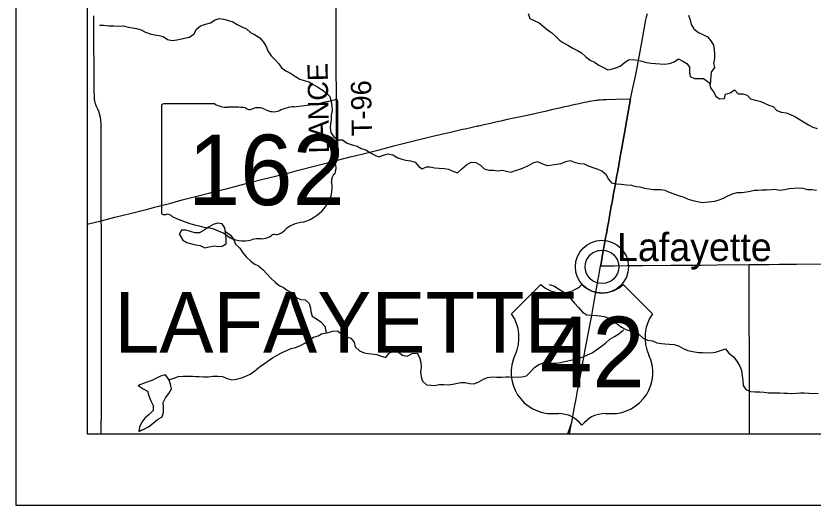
# Model space of a CAD drawing. Extents: x 0 to 34, y 0 to 22.
# Drawn here: x 2 to 3.119, y 14 to 14.686 of the extents above; entities that cross this region are included whole.
import ezdxf

# ---------------------------------------------------------------- set-up
doc = ezdxf.new("R2010")
doc.units = 0
for name, color, linetype in [('GM_X_County_Road', 7, 'Continuous'), ('GM_X_Minor_Lake', 7, 'Continuous'), ('GM_X_Minor_River', 7, 'Continuous'), ('GM_X_Rail_Line_Text', 7, 'Continuous'), ('GM_X_State_Location', 7, 'Continuous'), ('GM_X_State_Route', 7, 'Continuous'), ('GM_X_State_Shield', 7, 'Continuous'), ('GM_X_Township_Road', 7, 'Continuous'), ('GM_X_Township_Road_Text', 7, 'Continuous'), ('GM_X_Township_Text', 7, 'Continuous'), ('GM_X_Unincorporated', 7, 'Continuous'), ('GM_X_Unincorporated_Location', 7, 'Continuous'), ('GM_X_Unincorporated_Text', 7, 'Continuous'), ('GM_X_US_Location', 7, 'Continuous'), ('GM_X_US_Route', 7, 'Continuous'), ('GM_X_US_Shield', 7, 'Continuous'), ('SH_Cut_Line', 7, 'Continuous'), ('SH_Data', 7, 'Continuous')]:
    doc.layers.add(name, color=color, linetype=linetype)

msp = doc.modelspace()

# ---------------------------------------------------------------- linework, layer by layer
at = {"layer": 'GM_X_County_Road'}
msp.add_lwpolyline([(2.7775, 14.1), (2.7794, 14.1099), (2.7798, 14.1121), (2.7803, 14.1148), (2.7807, 14.1169)], dxfattribs=at)
at = {"layer": 'GM_X_Minor_Lake'}
for points in [[(2.2941, 14.3826), (2.2933, 14.3892), (2.2895, 14.3945), (2.2832, 14.3955), (2.2768, 14.3938), (2.2705, 14.3899), (2.2644, 14.3857), (2.2578, 14.3819), (2.2513, 14.3821), (2.2452, 14.3838), (2.2388, 14.3857), (2.2323, 14.3857), (2.2294, 14.3795)], [(2.2941, 14.383), (2.2933, 14.3892), (2.2895, 14.3945), (2.2832, 14.3955), (2.2768, 14.3938), (2.2705, 14.3899), (2.2644, 14.3857), (2.2578, 14.3819), (2.2513, 14.3821), (2.2452, 14.3838), (2.2388, 14.3857), (2.2323, 14.3857), (2.2296, 14.38)], [(2.2296, 14.38), (2.2342, 14.3718), (2.2398, 14.3684), (2.2464, 14.3665), (2.2525, 14.365), (2.2586, 14.3641), (2.2651, 14.361), (2.2714, 14.3624), (2.2782, 14.3639), (2.2851, 14.363), (2.2898, 14.3632), (2.2953, 14.3666), (2.2951, 14.3731), (2.2941, 14.383)], [(2.2298, 14.3797), (2.2342, 14.3718), (2.2398, 14.3684), (2.2464, 14.3665), (2.2525, 14.365), (2.2586, 14.3641), (2.2651, 14.361), (2.2714, 14.3624), (2.2782, 14.3639), (2.2851, 14.363), (2.2898, 14.3632), (2.2953, 14.3666), (2.2951, 14.3731), (2.2941, 14.383)], [(2.2148, 14.176), (2.21, 14.1827), (2.2032, 14.1808), (2.1965, 14.1774), (2.1908, 14.1747), (2.184, 14.1724), (2.1779, 14.1699), (2.1718, 14.1676), (2.1785, 14.1629), (2.1846, 14.1597), (2.1867, 14.1532), (2.1892, 14.1464), (2.1925, 14.1396), (2.1927, 14.1327), (2.1872, 14.1272), (2.181, 14.1221), (2.1766, 14.1162), (2.1736, 14.1095), (2.1725, 14.1034)], [(2.2147, 14.1762), (2.21, 14.1827), (2.2032, 14.1808), (2.1965, 14.1774), (2.1908, 14.1747), (2.184, 14.1724), (2.1779, 14.1699), (2.1718, 14.1676), (2.1785, 14.1629), (2.1846, 14.1597), (2.1867, 14.1532), (2.1892, 14.1464), (2.1925, 14.1396), (2.1927, 14.1327), (2.1872, 14.1272), (2.181, 14.1221), (2.1766, 14.1162), (2.1736, 14.1095), (2.1725, 14.1032)], [(2.1725, 14.1034), (2.1806, 14.1069), (2.1863, 14.1099), (2.1928, 14.1151), (2.199, 14.1202), (2.2053, 14.124), (2.207, 14.1303), (2.2072, 14.1371), (2.2069, 14.144), (2.2101, 14.1504), (2.2147, 14.1567), (2.2185, 14.1632), (2.2169, 14.1696), (2.2148, 14.176)], [(2.1728, 14.1035), (2.1806, 14.1069), (2.1863, 14.1099), (2.1928, 14.1151), (2.199, 14.1202), (2.2053, 14.124), (2.207, 14.1303), (2.2072, 14.1371), (2.2069, 14.144), (2.2101, 14.1504), (2.2147, 14.1567), (2.2185, 14.1632), (2.2169, 14.1696), (2.2146, 14.1765)]]:
    msp.add_lwpolyline(points, dxfattribs=at)
at = {"layer": 'GM_X_Minor_River'}
for points in [[(2.7193, 14.6897), (2.7218, 14.683), (2.7288, 14.6797), (2.7348, 14.6769), (2.7403, 14.6719), (2.7463, 14.667), (2.7523, 14.6625), (2.7577, 14.6579), (2.7633, 14.6526), (2.769, 14.6487), (2.775, 14.6452), (2.7818, 14.6413), (2.7886, 14.6377), (2.7944, 14.6346), (2.8002, 14.6288), (2.8062, 14.6243)], [(2.9443, 14.6874), (2.9467, 14.681), (2.9481, 14.6744), (2.9521, 14.6684), (2.9583, 14.6632), (2.9644, 14.6602), (2.971, 14.6572), (2.9758, 14.6516), (2.9795, 14.6455), (2.9806, 14.6392), (2.981, 14.6331), (2.9809, 14.6265), (2.9796, 14.6198), (2.9809, 14.6141), (2.9764, 14.6077), (2.9747, 14.5896)], [(2.1174, 14.6734), (2.1235, 14.6733), (2.1306, 14.6724), (2.1376, 14.6725), (2.1446, 14.6722), (2.1511, 14.6724), (2.1575, 14.6708), (2.1636, 14.6699), (2.1693, 14.6689), (2.1759, 14.6667), (2.182, 14.6637), (2.1884, 14.6615), (2.1944, 14.6599), (2.2009, 14.659), (2.2068, 14.6576), (2.213, 14.6533), (2.2194, 14.6518), (2.2257, 14.653), (2.2305, 14.6539), (2.2368, 14.6553), (2.2433, 14.6567), (2.2498, 14.6608), (2.2534, 14.6676), (2.2593, 14.6724), (2.2662, 14.6749), (2.2731, 14.6767), (2.2797, 14.6808), (2.2856, 14.6827), (2.292, 14.6819), (2.2983, 14.68), (2.3045, 14.678), (2.3107, 14.6745), (2.3172, 14.6713), (2.3236, 14.6684), (2.3292, 14.6631), (2.335, 14.6602), (2.3424, 14.6557), (2.3476, 14.6497), (2.3513, 14.6434), (2.3535, 14.6374), (2.3583, 14.6305), (2.3641, 14.6249), (2.3691, 14.6191), (2.3732, 14.6133), (2.3798, 14.6088), (2.3857, 14.6061), (2.3924, 14.6014), (2.3986, 14.5975), (2.4049, 14.5959), (2.4113, 14.5938), (2.4172, 14.5903), (2.4239, 14.5862), (2.43, 14.5827), (2.436, 14.5782), (2.441, 14.5734), (2.4426, 14.5665), (2.4435, 14.56), (2.4441, 14.5537), (2.4427, 14.5473), (2.4427, 14.5412), (2.4419, 14.5344), (2.4414, 14.5296), (2.4422, 14.5228), (2.4463, 14.5168), (2.4521, 14.5125), (2.4586, 14.5124), (2.465, 14.5079), (2.472, 14.5055), (2.479, 14.5035), (2.485, 14.5005), (2.4911, 14.4985), (2.4977, 14.4942), (2.5039, 14.4909), (2.5097, 14.4887), (2.5163, 14.4911), (2.5228, 14.493), (2.5294, 14.4916), (2.5362, 14.4871), (2.5418, 14.4855), (2.5475, 14.484), (2.5542, 14.483), (2.5608, 14.4811), (2.5656, 14.4752), (2.5705, 14.4716), (2.5765, 14.4746), (2.5814, 14.4745), (2.5881, 14.4732), (2.5945, 14.4727), (2.6012, 14.4724), (2.6076, 14.4715), (2.6135, 14.4686), (2.6199, 14.4664), (2.6263, 14.4718), (2.6325, 14.4774), (2.6392, 14.481), (2.646, 14.4807), (2.6524, 14.4772), (2.6575, 14.4716), (2.6639, 14.4698), (2.6704, 14.4698), (2.6763, 14.4692)], [(2.8062, 14.6243), (2.8123, 14.6215), (2.8187, 14.6174), (2.8249, 14.6139), (2.8313, 14.6109), (2.8378, 14.6122), (2.8426, 14.6134), (2.8485, 14.6161), (2.8543, 14.6206), (2.8604, 14.6247), (2.8665, 14.6253), (2.873, 14.6242), (2.8789, 14.6228), (2.8855, 14.621), (2.892, 14.6203), (2.898, 14.6196), (2.9043, 14.6191), (2.9108, 14.6188), (2.9176, 14.6196), (2.9245, 14.6222), (2.9303, 14.6261), (2.9363, 14.6227), (2.9422, 14.6196), (2.9459, 14.6144), (2.9459, 14.6075), (2.9466, 14.6014), (2.9528, 14.5985), (2.9593, 14.5984), (2.9656, 14.5984), (2.9739, 14.5924)], [(2.974, 14.5922), (2.9751, 14.5857), (2.9795, 14.5799), (2.9828, 14.5736), (2.9881, 14.5701), (2.995, 14.5704), (2.9966, 14.5768), (3.0029, 14.5784), (3.0092, 14.5826), (3.0143, 14.577), (3.0208, 14.5773), (3.0266, 14.5753), (3.0317, 14.5701), (3.0379, 14.5684), (3.0447, 14.5668), (3.051, 14.564), (3.0574, 14.5613), (3.0634, 14.5592), (3.0683, 14.5538), (3.0747, 14.5514), (3.0816, 14.5504), (3.0876, 14.5482), (3.0936, 14.5452), (3.1, 14.5417), (3.1059, 14.538), (3.1128, 14.5335), (3.1191, 14.5305), (3.1249, 14.5285)], [(2.6763, 14.4692), (2.6829, 14.4698), (2.6888, 14.4686), (2.6951, 14.4671), (2.7014, 14.4695), (2.7075, 14.4714), (2.7138, 14.4736), (2.7198, 14.4765), (2.7265, 14.4804), (2.7326, 14.482), (2.7394, 14.4789), (2.7458, 14.4765), (2.7529, 14.4775), (2.7592, 14.4783), (2.7657, 14.4793), (2.7722, 14.4821), (2.7783, 14.4837), (2.7851, 14.4809), (2.7917, 14.4792), (2.7978, 14.4787), (2.8036, 14.4758), (2.8103, 14.4736), (2.8159, 14.472), (2.8227, 14.469), (2.8286, 14.4641), (2.8317, 14.4578), (2.8365, 14.4522), (2.8435, 14.4506), (2.8498, 14.4503), (2.8574, 14.4494), (2.8646, 14.4487), (2.8703, 14.447), (2.876, 14.4464), (2.8826, 14.4449), (2.8893, 14.4437), (2.895, 14.443), (2.9062, 14.4428), (2.9111, 14.4421), (2.9172, 14.4392), (2.9238, 14.4368), (2.9304, 14.4342), (2.9378, 14.4319), (2.944, 14.4292), (2.9504, 14.4272), (2.9569, 14.4261), (2.9637, 14.4246), (2.9767, 14.4259), (2.9814, 14.4264), (2.9875, 14.4282), (2.9935, 14.4306), (2.9998, 14.4337), (3.0063, 14.4366), (3.013, 14.4388), (3.0191, 14.4386), (3.026, 14.4395), (3.0308, 14.4405), (3.0369, 14.4417), (3.042, 14.442), (3.0479, 14.4423), (3.0544, 14.4424), (3.0608, 14.4426), (3.0658, 14.4435), (3.0722, 14.4417), (3.0797, 14.4429), (3.086, 14.4443), (3.0925, 14.4447), (3.0989, 14.445), (3.1052, 14.4447), (3.1116, 14.443), (3.1174, 14.4429), (3.1242, 14.4421)], [(2.2941, 14.3841), (2.3012, 14.3787), (2.3059, 14.3723), (2.3084, 14.3662), (2.3142, 14.3606), (2.3185, 14.3538), (2.3237, 14.3477), (2.3292, 14.3428), (2.3346, 14.3384), (2.3408, 14.3356), (2.3472, 14.33), (2.353, 14.3242), (2.3578, 14.3182), (2.3638, 14.3127), (2.3698, 14.3083), (2.3757, 14.3053), (2.3824, 14.3004), (2.3887, 14.2975), (2.3937, 14.2913), (2.3997, 14.2883), (2.4062, 14.2879), (2.4118, 14.2828), (2.4138, 14.2763), (2.4139, 14.2714), (2.4159, 14.2649), (2.4219, 14.2612), (2.4281, 14.2569), (2.4337, 14.2511), (2.4358, 14.2416)], [(2.7486, 14.3096), (2.7551, 14.3076), (2.762, 14.3035), (2.7681, 14.2996), (2.7741, 14.2955), (2.7791, 14.2895), (2.7845, 14.2833), (2.7901, 14.2771), (2.7957, 14.2707), (2.8019, 14.2668), (2.8084, 14.2663), (2.8148, 14.266), (2.8196, 14.2656), (2.826, 14.2647), (2.8325, 14.2623), (2.8383, 14.2588), (2.8443, 14.2545), (2.8505, 14.2494), (2.8565, 14.2463), (2.8626, 14.2443), (2.869, 14.2419), (2.8751, 14.2393), (2.8809, 14.2342), (2.8869, 14.2313), (2.8937, 14.2304), (2.8998, 14.2278), (2.9066, 14.2268), (2.9114, 14.2263), (2.9178, 14.2258), (2.9241, 14.2253), (2.9305, 14.2235), (2.9369, 14.2197), (2.9434, 14.217), (2.9504, 14.2155), (2.9581, 14.2142), (2.9642, 14.2139), (2.9755, 14.2137), (2.9823, 14.2146), (2.9892, 14.2169), (2.9963, 14.2191), (3.0013, 14.2133), (3.0075, 14.2082), (3.0125, 14.202), (3.0166, 14.1951), (3.0188, 14.1886), (3.02, 14.1816), (3.0208, 14.1747), (3.0211, 14.1677), (3.0248, 14.1621), (3.0314, 14.1595), (3.0379, 14.159), (3.0445, 14.1589), (3.0508, 14.1586), (3.0567, 14.1574), (3.0614, 14.1576), (3.0726, 14.1574), (3.0787, 14.157), (3.0835, 14.1569), (3.0897, 14.1566), (3.0962, 14.157), (3.1016, 14.1573), (3.1069, 14.1574), (3.1132, 14.1569), (3.1265, 14.1567)], [(2.2153, 14.1756), (2.2219, 14.1779), (2.2284, 14.1805), (2.235, 14.1809), (2.2415, 14.181), (2.248, 14.1809), (2.2527, 14.1804), (2.2575, 14.1802), (2.2634, 14.1797), (2.2702, 14.1801), (2.2767, 14.1808), (2.2837, 14.1808), (2.2902, 14.1803), (2.2966, 14.1775), (2.303, 14.1759), (2.3099, 14.1767), (2.3168, 14.1785), (2.3229, 14.1807), (2.3291, 14.1838), (2.3356, 14.1884), (2.3416, 14.1933), (2.3474, 14.1977), (2.3543, 14.2022), (2.3605, 14.2068), (2.3666, 14.2105), (2.3731, 14.2136), (2.3799, 14.2169), (2.3864, 14.2196), (2.3925, 14.2212), (2.3986, 14.2232), (2.4055, 14.2271), (2.4117, 14.2317), (2.4177, 14.2354), (2.4242, 14.2374), (2.429, 14.2403), (2.4383, 14.2423)], [(2.4383, 14.2422), (2.445, 14.2438), (2.4515, 14.2443), (2.4575, 14.2398), (2.4633, 14.2365), (2.4701, 14.2341), (2.4748, 14.2285), (2.4762, 14.222), (2.4826, 14.2166), (2.489, 14.2134), (2.4951, 14.2125), (2.4998, 14.2121), (2.5066, 14.2112), (2.5127, 14.2088), (2.5195, 14.207), (2.5236, 14.2126), (2.5301, 14.2165), (2.5371, 14.2144), (2.5428, 14.2102), (2.5496, 14.2089), (2.5565, 14.2129), (2.5634, 14.2132), (2.5667, 14.2071), (2.5685, 14.2002), (2.5691, 14.1933), (2.5682, 14.1865), (2.5689, 14.18), (2.5709, 14.1737), (2.5767, 14.1685), (2.5831, 14.168), (2.5879, 14.1679), (2.5942, 14.1693), (2.6005, 14.1692), (2.6069, 14.1689), (2.6136, 14.1697), (2.6201, 14.1709), (2.6249, 14.1718), (2.6306, 14.1721), (2.6368, 14.1705), (2.6433, 14.1701), (2.6502, 14.1727), (2.6565, 14.1767), (2.6623, 14.1789), (2.6686, 14.18), (2.675, 14.1795), (2.6819, 14.1793), (2.688, 14.18), (2.6927, 14.1797), (2.7057, 14.1795), (2.7106, 14.1798), (2.7171, 14.1815), (2.7227, 14.187), (2.728, 14.1929), (2.7341, 14.1972), (2.7406, 14.1994), (2.7454, 14.1991), (2.752, 14.1992), (2.7585, 14.199), (2.7646, 14.1999), (2.7709, 14.2013), (2.7772, 14.2029), (2.7833, 14.2043), (2.7898, 14.2057), (2.7967, 14.208), (2.8028, 14.2106), (2.8092, 14.2137), (2.8157, 14.2183), (2.8223, 14.2228), (2.8281, 14.2272), (2.8342, 14.233), (2.8404, 14.2367), (2.8467, 14.2404), (2.8531, 14.246)]]:
    msp.add_lwpolyline(points, dxfattribs=at)
at = {"layer": 'GM_X_Rail_Line_Text'}
msp.add_lwpolyline([(3.3082, 15.6075), (3.1191, 15.6057), (3.0847, 15.6056), (2.7419, 15.6026), (2.5905, 15.6012), (2.4495, 15.6), (2.3157, 15.5986), (2.1086, 15.5977), (2.1, 15.5976), (2.1, 14.1), (4.2989, 14.1)], dxfattribs=at)
at = {"layer": 'GM_X_State_Route'}
for points in [[(2.1, 14.3941), (2.102, 14.3946), (2.1197, 14.3989), (2.139, 14.4039), (2.1625, 14.4097), (2.1864, 14.4159), (2.1947, 14.418), (2.2174, 14.4238), (2.2335, 14.4281), (2.2595, 14.4348), (2.2708, 14.4377), (2.2791, 14.4399), (2.2893, 14.4425), (2.2953, 14.4439), (2.3305, 14.453), (2.3467, 14.4571), (2.3741, 14.4639), (2.3785, 14.465), (2.3949, 14.4693), (2.4223, 14.4763), (2.4488, 14.4832), (2.4515, 14.484), (2.4714, 14.4891), (2.4777, 14.4907), (2.4816, 14.4917), (2.4855, 14.4926), (2.5005, 14.4963), (2.5099, 14.4987), (2.5169, 14.5004), (2.5305, 14.504), (2.5531, 14.5097), (2.5679, 14.5133), (2.5757, 14.5152), (2.5874, 14.5181), (2.5916, 14.5191), (2.5993, 14.5209), (2.6084, 14.523), (2.6158, 14.5247), (2.6272, 14.5273), (2.631, 14.5281), (2.6387, 14.5299), (2.6481, 14.532), (2.6498, 14.5323), (2.6573, 14.534), (2.6664, 14.536), (2.6683, 14.5364), (2.6758, 14.5381), (2.6831, 14.5397), (2.6863, 14.5404), (2.6871, 14.5406), (2.6901, 14.5413), (2.697, 14.5428), (2.7038, 14.5442), (2.7109, 14.5457), (2.7177, 14.5472), (2.7286, 14.5496), (2.7323, 14.5504), (2.7406, 14.5523), (2.7456, 14.5534), (2.7523, 14.5549), (2.7564, 14.5559), (2.7657, 14.558), (2.7685, 14.5586), (2.7761, 14.5603), (2.778, 14.5607), (2.7836, 14.5619), (2.7907, 14.5635), (2.7965, 14.5648), (2.7986, 14.5652), (2.802, 14.5659), (2.8056, 14.5666), (2.8119, 14.5677), (2.8142, 14.5681), (2.816, 14.5683), (2.8181, 14.5685), (2.8207, 14.5688), (2.8242, 14.5691), (2.8291, 14.5693), (2.8424, 14.5697), (2.8631, 14.5702)], [(2.8631, 14.5702), (2.8564, 14.5331), (2.8558, 14.5299), (2.8512, 14.5042), (2.8511, 14.5035), (2.8503, 14.4988), (2.8485, 14.4889), (2.8464, 14.4769), (2.8446, 14.4669), (2.8439, 14.463), (2.8428, 14.4573), (2.8409, 14.4463), (2.8393, 14.4373), (2.838, 14.4304), (2.8372, 14.4256), (2.8366, 14.4226), (2.8364, 14.4214), (2.836, 14.4191), (2.8354, 14.416), (2.8341, 14.4085), (2.834, 14.4078), (2.8319, 14.3963), (2.8307, 14.3899), (2.8296, 14.3835), (2.8288, 14.3789), (2.8285, 14.3776), (2.8281, 14.3752), (2.8276, 14.3724), (2.8242, 14.3533), (2.8238, 14.3515), (2.8228, 14.3456), (2.8216, 14.3392), (2.821, 14.3358)], [(2.821, 14.3358), (2.8399, 14.3359), (2.859, 14.3361), (2.8805, 14.3362), (2.9198, 14.3364), (2.932, 14.3365), (2.9426, 14.3365), (2.9529, 14.3367), (2.9624, 14.3367), (2.9848, 14.3369), (3.0294, 14.3374), (3.0498, 14.3376), (3.0577, 14.3378), (3.0716, 14.338), (3.0963, 14.3382), (3.1434, 14.3384)]]:
    msp.add_lwpolyline(points, dxfattribs=at)
at = {"layer": 'GM_X_State_Shield'}
for p, q in [((2.2794, 14.563), (2.207, 14.563)), ((2.4518, 14.4882), (2.4518, 14.5667)), ((2.2046, 14.5604), (2.2046, 14.4103)), ((2.4517, 14.4882), (2.4518, 14.4882))]:
    msp.add_line(p, q, dxfattribs=at)
for centre, major_axis, start_param, end_param in [((2.2074, 14.5607), (0.00286, 0), 1.712693, 3.28349), ((2.2966, 14.5804), (0.0278, 0), 4.042523, 4.731795), ((2.3637, 14.7676), (0.2621, 0), 4.814394, 5.042369), ((2.449, 14.567), (0.00275, 0), 6.141152, 7.989035), ((2.3058, 14.4787), (0.0997, 0), 1.404758, 1.657858), ((2.3285, 14.5615), (0.00801, 0), 3.836095, 5.185415), ((2.3402, 14.5442), (0.0167, 0), 0.950623, 2.079405), ((2.3618, 14.568), (0.02, 0), 4.081561, 5.145723), ((2.3971, 14.5172), (0.0527, 0), 1.699011, 2.107814), ((2.4511, 14.4824), (0.00426, 0), 1.883978, 3.671073), ((2.4488, 14.4879), (0.00294, 0), 5.05454, 6.418171), ((2.424, 14.4725), (0.0256, 0), 5.934695, 6.695948), ((2.4616, 14.4553), (0.0186, 0), 2.387724, 3.262537), ((2.3784, 14.4454), (0.0656, 0), 5.101752, 6.440018), ((2.2074, 14.41), (0.00289, 0), 3.00124, 4.508301), ((2.2079, 14.4253), (0.022, 0), 4.665946, 4.897461), ((2.2124, 14.4017), (0.00795, 0), 0.519207, 1.627899), ((2.3127, 14.5365), (0.1893, 0), 4.195997, 4.488961), ((2.406, 14.3682), (0.0359, 0), 1.647645, 2.488434), ((2.2563, 14.3429), (0.0592, 0), 0.823519, 1.323587), ((2.3605, 14.3958), (0.0212, 0), 4.937069, 5.64225), ((2.3204, 14.4009), (0.0376, 0), 4.026481, 4.996735), ((2.3421, 14.349), (0.0309, 0), 1.495662, 1.94098), ((2.3448, 14.3897), (0.02, 0), 4.691044, 5.507374), ((2.3629, 14.3751), (0.00564, 0), 1.147584, 2.315152)]:
    msp.add_ellipse(centre, major_axis=major_axis, ratio=0.8, start_param=start_param, end_param=end_param, dxfattribs=at)
at = {"layer": 'GM_X_Township_Road'}
for points in [[(2.4515, 14.484), (2.4507, 14.4872), (2.4506, 14.488), (2.4504, 14.489), (2.4503, 14.49), (2.4501, 14.5085), (2.4501, 14.5448), (2.4498, 14.6441), (2.4496, 14.7787)], [(2.1197, 14.4634), (2.1197, 14.508), (2.1197, 14.5198), (2.1196, 14.5317), (2.1195, 14.5365), (2.1194, 14.5385), (2.1193, 14.5396), (2.1191, 14.5415), (2.1188, 14.5434), (2.1185, 14.545), (2.1182, 14.5463), (2.1174, 14.5491), (2.1162, 14.5521), (2.1148, 14.5555), (2.1128, 14.5603), (2.1115, 14.5637), (2.111, 14.5656), (2.1106, 14.5671), (2.1103, 14.5687), (2.1102, 14.5703), (2.1101, 14.5722), (2.1099, 14.5821), (2.1098, 14.5937), (2.1098, 14.6005), (2.1097, 14.6058), (2.1097, 14.6272), (2.1096, 14.6344), (2.1095, 14.6597), (2.1095, 14.6703), (2.1094, 14.6867)], [(2.1197, 14.3989), (2.1197, 14.4553), (2.1197, 14.4634)], [(2.1197, 14.1), (2.1198, 14.1094), (2.12, 14.1296), (2.1201, 14.1418), (2.1201, 14.1536), (2.1201, 14.1656), (2.1201, 14.1774), (2.1202, 14.1893), (2.1202, 14.2012), (2.1203, 14.217), (2.1202, 14.2484), (2.1201, 14.2749), (2.1201, 14.2906), (2.1201, 14.3295), (2.1201, 14.3808), (2.12, 14.3925), (2.1199, 14.3967), (2.1197, 14.3989)], [(3.0302, 14.1), (3.0302, 14.1286), (3.03, 14.1974), (3.0296, 14.2755), (3.0294, 14.3374)]]:
    msp.add_lwpolyline(points, dxfattribs=at)
at = {"layer": 'GM_X_Unincorporated'}
for radius in [0.0372, 0.0236]:
    msp.add_circle((2.8229, 14.3343), radius, dxfattribs=at)
at = {"layer": 'GM_X_Unincorporated_Location'}
msp.add_line((2.8229, 14.3343), (2.8229, 14.3343), dxfattribs=at)
at = {"layer": 'GM_X_US_Route'}
for points in [[(2.8738, 14.6214), (2.8757, 14.6313), (2.8802, 14.6571), (2.8839, 14.6787), (2.8855, 14.6853), (2.8868, 14.69)], [(2.8631, 14.5702), (2.8667, 14.5873), (2.8703, 14.6043), (2.8723, 14.6136), (2.8738, 14.6214)], [(2.821, 14.3358), (2.8216, 14.3392), (2.8228, 14.3456), (2.8238, 14.3515), (2.8242, 14.3533), (2.8276, 14.3724), (2.8281, 14.3752), (2.8285, 14.3776), (2.8288, 14.3789), (2.8296, 14.3835), (2.8307, 14.3899), (2.8319, 14.3963), (2.834, 14.4078), (2.8341, 14.4085), (2.8354, 14.416), (2.836, 14.4191), (2.8364, 14.4214), (2.8366, 14.4226), (2.8372, 14.4256), (2.838, 14.4304), (2.8393, 14.4373), (2.8409, 14.4463), (2.8428, 14.4573), (2.8439, 14.463), (2.8446, 14.4669), (2.8464, 14.4769), (2.8485, 14.4889), (2.8503, 14.4988), (2.8511, 14.5035), (2.8512, 14.5042), (2.8558, 14.5299), (2.8564, 14.5331), (2.8631, 14.5702)], [(2.7752, 14.1), (2.7793, 14.1122), (2.7797, 14.1134), (2.78, 14.1146), (2.7804, 14.1158), (2.7807, 14.1169), (2.7815, 14.1216), (2.782, 14.1244), (2.7845, 14.1378), (2.7849, 14.1399), (2.7853, 14.1421), (2.7862, 14.1465), (2.7876, 14.1543), (2.7877, 14.1546), (2.7892, 14.1632), (2.7894, 14.164), (2.7918, 14.1772), (2.7932, 14.1843), (2.7965, 14.2024), (2.7978, 14.2095), (2.7989, 14.2153), (2.8061, 14.252), (2.8086, 14.2662), (2.8116, 14.2827), (2.8176, 14.3171), (2.8194, 14.3269), (2.821, 14.3358)]]:
    msp.add_lwpolyline(points, dxfattribs=at)
at = {"layer": 'GM_X_US_Shield'}
for p, q in [((2.7372, 14.3096), (2.696, 14.2684)), ((2.8937, 14.2684), (2.8525, 14.3096)), ((2.7536, 14.1284), (2.7619, 14.1284)), ((2.8278, 14.1284), (2.836, 14.1284))]:
    msp.add_line(p, q, dxfattribs=at)
for centre, radius, start, end in [((2.766, 14.3391), 0.0412, 225.573, 314.427), ((2.8237, 14.3391), 0.0412, 225.573, 314.427), ((2.6487, 14.2353), 0.0577, 334.5471, 35.0009), ((2.941, 14.2353), 0.0577, 144.9991, 205.4529), ((2.753, 14.186), 0.0577, 154.8319, 270.6383), ((2.8367, 14.186), 0.0577, 269.3617, 25.1681), ((2.7619, 14.0872), 0.0412, 36.8699, 90), ((2.8278, 14.0872), 0.0412, 90, 143.1301)]:
    msp.add_arc(centre, radius, start, end, dxfattribs=at)
at = {"layer": 'SH_Cut_Line'}
msp.add_lwpolyline([(2.1, 20.3942), (2.1, 14.1), (8.9, 14.1)], dxfattribs=at)
at = {"layer": 'SH_Data'}
for p, q in [((2, 21), (2, 14)), ((2.1, 20.9), (2.1, 14.1)), ((2.1, 14.1), (8.9, 14.1)), ((2.1, 14.1), (2.1, 14.1)), ((2, 14), (9, 14))]:
    msp.add_line(p, q, dxfattribs=at)

# ---------------------------------------------------------------- texts
at = {"layer": 'GM_X_State_Location'}
for s in ['s', 'r']:
    msp.add_text(s, height=0.0000947, dxfattribs=at).set_placement((2.3366, 14.4431))
msp.add_text('162', height=0.0000947, rotation=0, dxfattribs=at).set_placement((2.3032, 14.4362))
at = {"layer": 'GM_X_State_Shield'}
msp.add_text('162', height=0.09888, dxfattribs=at).set_placement((2.2413, 14.4209))
at = {"layer": 'GM_X_Township_Road_Text'}
for s, rotation, p in [('LANCE', 91.0306, (2.4399, 14.4938)), ('T-96', 91.061, (2.5, 14.5182))]:
    msp.add_text(s, height=0.02841, rotation=rotation, dxfattribs=at).set_placement(p)
at = {"layer": 'GM_X_Township_Text'}
msp.add_text('LAFAYETTE', height=0.08523, rotation=0, dxfattribs=at).set_placement((2.138, 14.2138))
at = {"layer": 'GM_X_Unincorporated_Text'}
msp.add_text('Lafayette', height=0.03949, rotation=0, dxfattribs=at).set_placement((2.844, 14.3423))
at = {"layer": 'GM_X_US_Location'}
for s in ['0', '/']:
    msp.add_text(s, height=0.0000947, dxfattribs=at).set_placement((2.7948, 14.1979))
msp.add_text('42', height=0.0000947, rotation=0, dxfattribs=at).set_placement((2.7753, 14.1783))
at = {"layer": 'GM_X_US_Shield'}
msp.add_text('42', height=0.09888, dxfattribs=at).set_placement((2.7358, 14.1654))

doc.saveas('drawing.dxf')
